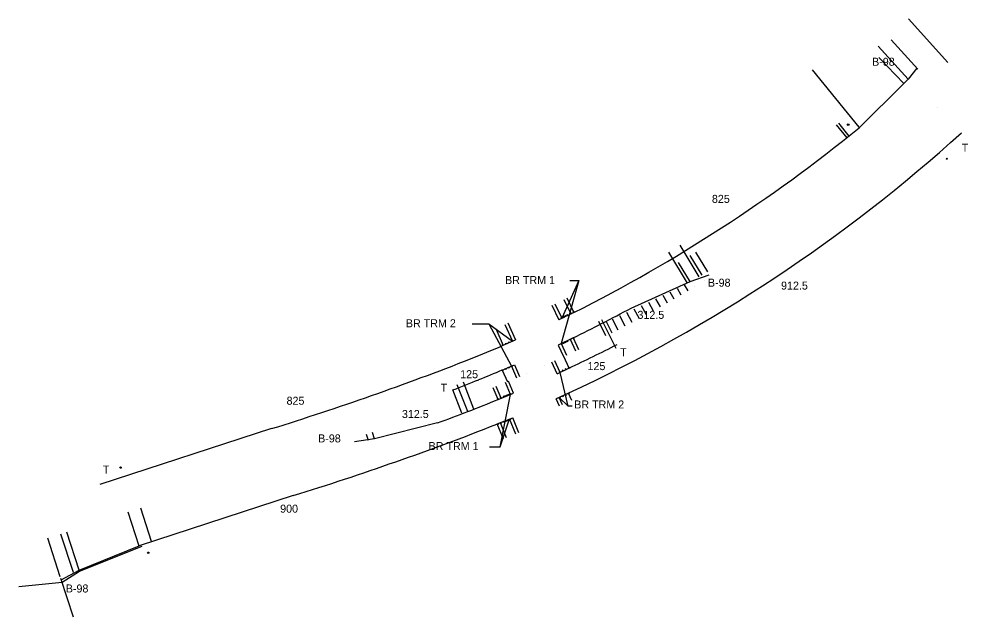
# Model space of a CAD drawing. Extents: x 1394788 to 1443949, y 571575 to 592763.
# Drawn here: x 1434855 to 1436634, y 586575 to 587696 of the extents above; entities that cross this region are included whole.
import ezdxf

# ---------------------------------------------------------------- set-up
doc = ezdxf.new("R2010")
doc.units = 0
doc.layers.add('Level 24', color=7, linetype='Continuous')
doc.layers.add('Level 62', color=7, linetype='Continuous')

msp = doc.modelspace()

# ---------------------------------------------------------------- linework, layer by layer
at = {"layer": 'Level 24'}
for p, q in [((1436538.8, 587603.5), (1436522.4, 587582.8)), ((1436522.4, 587582.8), (1436514.1, 587574.8)), ((1436514.1, 587574.8), (1436430.5, 587492.1)), ((1436113.3, 587203.9), (1436149.3, 587216.3)), ((1436002.7, 587153.9), (1436113.3, 587203.9)), ((1435895.8, 587145.8), (1435867.7, 587132.1)), ((1435763.1, 587084.4), (1435786, 587094.3)), ((1435894.2, 587098.3), (1435866, 587084.8)), ((1435761.4, 587038), (1435784.3, 587047.8)), ((1435886.8, 587041.7), (1435863.5, 587030.5)), ((1435717.5, 587019.9), (1435717.5, 587019.9)), ((1435753.7, 586982.8), (1435782.6, 586994.9)), ((1435885.3, 586994.4), (1435862.5, 586984.1)), ((1435752, 586936.8), (1435781, 586948.6)), ((1435328.7, 586928.1), (1435007.2, 586823.7)), ((1435639.8, 586938.7), (1435522, 586909.1)), ((1435751.2, 586936.4), (1435751.1, 586936.4)), ((1435522, 586909.1), (1435484.4, 586903.4)), ((1435369.5, 586802.5), (1435369.5, 586802.5)), ((1434968.3, 586662.6), (1435080.4, 586708.7)), ((1434934.6, 586644.8), (1434968.3, 586662.6))]:
    msp.add_line(p, q, dxfattribs=at)
for points in [[(1435872.6, 587134.5), (1435871.9, 587135.9), (1435873.4, 587136.6), (1435874.1, 587135.2)], [(1435875.4, 587135.9), (1435874.7, 587137.3), (1435876.2, 587138), (1435876.9, 587136.6)], [(1435878.2, 587137.2), (1435877.5, 587138.6), (1435879, 587139.4), (1435879.7, 587138)], [(1435881, 587138.6), (1435880.3, 587140), (1435881.8, 587140.7), (1435882.5, 587139.3)], [(1435883.8, 587140), (1435883.1, 587141.4), (1435884.6, 587142.1), (1435885.3, 587140.7)], [(1435889.4, 587142.7), (1435888.7, 587144.2), (1435890.2, 587144.9), (1435890.9, 587143.5)], [(1435895, 587145.5), (1435894.3, 587146.9), (1435895.8, 587147.7), (1435896.5, 587146.3)], [(1435762.3, 587084), (1435761.7, 587085.5), (1435763.2, 587086.1), (1435763.9, 587084.7)], [(1435768.1, 587086.5), (1435767.4, 587087.9), (1435769, 587088.6), (1435769.6, 587087.1)], [(1435773.8, 587089), (1435773.2, 587090.4), (1435774.7, 587091.1), (1435775.3, 587089.6)], [(1435779.5, 587091.4), (1435778.9, 587092.9), (1435780.5, 587093.5), (1435781.1, 587092.1)], [(1435871.6, 587085.7), (1435870.9, 587087.1), (1435872.4, 587087.9), (1435873.1, 587086.4)], [(1435874.4, 587087.1), (1435873.7, 587088.5), (1435875.3, 587089.2), (1435875.9, 587087.8)], [(1435877.2, 587088.4), (1435876.6, 587089.8), (1435878.1, 587090.6), (1435878.7, 587089.1)], [(1435880.1, 587089.8), (1435879.4, 587091.2), (1435880.9, 587091.9), (1435881.6, 587090.5)], [(1435882.9, 587091.1), (1435882.2, 587092.5), (1435883.7, 587093.3), (1435884.4, 587091.8)], [(1435888.5, 587093.8), (1435887.8, 587095.2), (1435889.3, 587096), (1435890, 587094.6)], [(1435894.1, 587096.6), (1435893.5, 587098), (1435895, 587098.7), (1435895.6, 587097.3)], [(1435761.2, 587036.3), (1435760.6, 587037.8), (1435762.1, 587038.4), (1435762.7, 587037)], [(1435766.9, 587038.7), (1435766.3, 587040.2), (1435767.9, 587040.8), (1435768.5, 587039.4)], [(1435772.7, 587041.2), (1435772.1, 587042.6), (1435773.6, 587043.3), (1435774.2, 587041.8)], [(1435778.4, 587043.6), (1435777.8, 587045), (1435779.4, 587045.7), (1435780, 587044.3)], [(1435869.1, 587033.3), (1435868.5, 587034.7), (1435870, 587035.4), (1435870.6, 587034)], [(1435874.8, 587035.9), (1435874.1, 587037.4), (1435875.6, 587038.1), (1435876.3, 587036.7)], [(1435880.4, 587038.6), (1435879.8, 587040), (1435881.3, 587040.8), (1435881.9, 587039.3)], [(1435886.1, 587041.3), (1435885.4, 587042.7), (1435886.9, 587043.4), (1435887.6, 587042)], [(1435885.1, 586992.8), (1435884.5, 586994.2), (1435886, 586994.9), (1435886.6, 586993.5)], [(1435752.8, 586982.5), (1435752.2, 586983.9), (1435753.7, 586984.6), (1435754.4, 586983.1)], [(1435758.6, 586984.9), (1435758, 586986.3), (1435759.5, 586987), (1435760.1, 586985.5)], [(1435764.4, 586987.2), (1435763.8, 586988.7), (1435765.3, 586989.3), (1435765.9, 586987.9)], [(1435767.3, 586988.4), (1435766.7, 586989.9), (1435768.2, 586990.5), (1435768.8, 586989.1)], [(1435770.1, 586989.6), (1435769.5, 586991.1), (1435771.1, 586991.7), (1435771.7, 586990.3)], [(1435773, 586990.8), (1435772.4, 586992.3), (1435774, 586992.9), (1435774.6, 586991.5)], [(1435775.9, 586992), (1435775.3, 586993.5), (1435776.9, 586994.1), (1435777.5, 586992.7)], [(1435868.1, 586984.9), (1435867.5, 586986.3), (1435869, 586987), (1435869.6, 586985.6)], [(1435873.8, 586987.5), (1435873.1, 586988.9), (1435874.7, 586989.6), (1435875.3, 586988.2)], [(1435879.5, 586990.1), (1435878.8, 586991.6), (1435880.3, 586992.3), (1435881, 586990.8)], [(1435763.4, 586939.8), (1435762.8, 586941.2), (1435764.4, 586941.9), (1435765, 586940.4)], [(1435766.3, 586940.9), (1435765.7, 586942.4), (1435767.3, 586943), (1435767.9, 586941.6)], [(1435769.2, 586942.1), (1435768.6, 586943.6), (1435770.2, 586944.2), (1435770.8, 586942.7)], [(1435772.1, 586943.3), (1435771.5, 586944.7), (1435773.1, 586945.4), (1435773.7, 586943.9)], [(1435775, 586944.5), (1435774.4, 586945.9), (1435776, 586946.5), (1435776.5, 586945.1)], [(1435751.8, 586935.1), (1435751.2, 586936.6), (1435752.8, 586937.2), (1435753.4, 586935.8)], [(1435757.6, 586937.4), (1435757, 586938.9), (1435758.6, 586939.5), (1435759.2, 586938.1)]]:
    msp.add_lwpolyline(points, close=True, dxfattribs=at)
msp.add_lwpolyline([(1435369.5, 586802.5), (1435080.4, 586708.7)], dxfattribs=at)
for centre, radius, start, end in [((1434643.7, 589670.2), 2949.6, 294.8914, 312.1307), ((1434568.8, 589780.8), 2950.3, 296.7297, 309.125), ((1434653.9, 589654.1), 2840.8, 295.8869, 298.3505), ((1433689.9, 591964.3), 5302.1, 292.2998, 293.0177), ((1434653.9, 589654.1), 2888.8, 295.2645, 297.2479), ((1433674.6, 592246.1), 5569.3, 287.278, 291.3457), ((1434653.9, 589654.1), 2840.8, 291.9864, 292.9439), ((1434580.9, 589836.4), 3037.2, 290.9855, 291.9756), ((1434653.9, 589654.1), 2888.8, 289.9535, 292.378), ((1433712.1, 592139.3), 5588.2, 287.2529, 291.4008), ((1434653.9, 589654.1), 2930.8, 291.9864, 292.0045)]:
    msp.add_arc(centre, radius, start, end, dxfattribs=at)
at = {"layer": 'Level 62'}
for p, q in [((1436522.6, 587695.9), (1436596.7, 587614.1)), ((1436490.4, 587656.9), (1436540.3, 587601.8)), ((1436466.2, 587644.9), (1436522.4, 587582.8)), ((1436467.1, 587623.6), (1436514.1, 587574.8)), ((1436342.4, 587600.4), (1436429.9, 587493)), ((1436576.7, 587530.4), (1436576.7, 587530.4)), ((1436387.6, 587497.8), (1436407.2, 587473.3)), ((1436391.5, 587500.9), (1436411.1, 587476.5)), ((1436094.2, 587271.8), (1436130.1, 587212.4)), ((1436072.8, 587258.9), (1436108, 587200.8)), ((1436112.8, 587252.6), (1436135.3, 587215.6)), ((1436123.5, 587259.1), (1436146, 587222.1)), ((1436091.4, 587239.6), (1436113.9, 587202.6)), ((1435905.1, 587205.8), (1435871.7, 587087.5)), ((1435905.1, 587205.8), (1435873.3, 587134.9)), ((1435887.8, 587205.8), (1435905.1, 587205.8)), ((1436089, 587191.2), (1436096.2, 587178.8)), ((1436102.4, 587197.8), (1436109.2, 587186.4)), ((1436122.1, 587194), (1436122.1, 587194)), ((1436141.3, 587205.7), (1436141.3, 587205.7)), ((1435882.7, 587173), (1435895.8, 587145.8)), ((1436062.2, 587178), (1436070.2, 587163.8)), ((1436075.6, 587184.5), (1436083.2, 587171.3)), ((1436096.2, 587178.8), (1436096.2, 587178.8)), ((1436109.2, 587186.4), (1436109.2, 587186.4)), ((1435854.5, 587159.3), (1435867.7, 587132.1)), ((1435860.2, 587162.1), (1435873.3, 587134.9)), ((1435877, 587170.2), (1435890.2, 587143)), ((1436021.7, 587158.8), (1436030.9, 587141.9)), ((1436035.2, 587165.1), (1436044.1, 587149.1)), ((1436048.7, 587171.5), (1436057.2, 587156.5)), ((1436057.2, 587156.5), (1436057.2, 587156.5)), ((1436070.2, 587163.8), (1436070.2, 587163.8)), ((1436083.2, 587171.3), (1436083.2, 587171.3)), ((1435980.9, 587140.2), (1435991.3, 587120.6)), ((1435994.5, 587146.3), (1436004.5, 587127.6)), ((1436008.1, 587152.5), (1436017.7, 587134.7)), ((1436030.9, 587141.9), (1436030.9, 587141.9)), ((1436044.1, 587149.1), (1436044.1, 587149.1)), ((1435704.8, 587124.6), (1435736, 587124.6)), ((1435736, 587124.6), (1435780.3, 587091.8)), ((1435736, 587124.6), (1435778.6, 587045.4)), ((1435766.3, 587123.6), (1435780.3, 587091.8)), ((1435772.1, 587126.1), (1435786, 587094.3)), ((1435955.8, 587102.2), (1435942.1, 587128.8)), ((1435975.2, 587078.4), (1435947.8, 587131.8)), ((1435956, 587129), (1435966.9, 587107.9)), ((1435967.3, 587134.2), (1435978, 587113.6)), ((1435991.3, 587120.6), (1435991.3, 587120.6)), ((1436004.5, 587127.6), (1436004.5, 587127.6)), ((1436017.7, 587134.7), (1436017.7, 587134.7)), ((1435749.2, 587116), (1435763.1, 587084.2)), ((1435966.9, 587107.9), (1435966.9, 587107.9)), ((1435978, 587113.6), (1435978, 587113.6)), ((1435866, 587084.8), (1435876.3, 587063.1)), ((1435871.7, 587087.5), (1435882, 587065.8)), ((1435888.6, 587095.5), (1435898.9, 587073.9)), ((1435894.2, 587098.3), (1435904.5, 587076.5)), ((1435882, 587065.8), (1435882, 587065.8)), ((1435902.1, 587075.5), (1435902.1, 587075.5)), ((1435784.3, 587047.8), (1435793.8, 587025.8)), ((1435864.2, 587031), (1435854.1, 587052.8)), ((1435859.8, 587055.4), (1435859.8, 587055.4)), ((1435869.9, 587033.6), (1435859.8, 587055.4)), ((1435886.9, 587041.5), (1435876.8, 587063.3)), ((1435761.4, 587038), (1435770.9, 587015.9)), ((1435778.6, 587045.4), (1435788.1, 587023.3)), ((1435806.8, 587031.5), (1435806.8, 587031.5)), ((1435840.9, 587046.7), (1435840.9, 587046.7)), ((1435885.1, 586970.1), (1435869.9, 587033.6)), ((1435708.3, 586964.5), (1435688.7, 587014.9)), ((1435767.5, 587014.5), (1435767.5, 587014.5)), ((1435776.8, 586992.4), (1435767.5, 587014.5)), ((1435782.6, 586994.9), (1435773.2, 587017)), ((1435788.1, 587023.3), (1435788.1, 587023.3)), ((1435685.6, 586956.9), (1435668.6, 587000.7)), ((1435696.6, 586960), (1435677.1, 587010.3)), ((1435753.8, 586982.7), (1435744.5, 587004.8)), ((1435749.9, 587007.2), (1435749.9, 587007.2)), ((1435759.5, 586985.1), (1435750.2, 587007.3)), ((1435891.5, 586980.7), (1435885.3, 586994.4)), ((1435757.7, 586893.9), (1435776.8, 586992.4)), ((1435868.8, 586970.4), (1435862.5, 586984.1)), ((1435874.5, 586973), (1435868.2, 586986.7)), ((1435885.1, 586970.1), (1435868.2, 586986.7)), ((1435892.4, 586970.1), (1435885.1, 586970.1)), ((1435757.7, 586893.9), (1435775.2, 586946.2)), ((1435786.9, 586918), (1435775.2, 586946.2)), ((1435792.6, 586920.4), (1435781, 586948.6)), ((1435763.8, 586908.5), (1435752, 586936.8)), ((1435769.5, 586910.8), (1435757.9, 586939.1)), ((1435507.1, 586917.3), (1435507.1, 586917.3)), ((1435510.9, 586905.9), (1435507.1, 586917.3)), ((1435522, 586909.1), (1435518, 586921)), ((1435737.3, 586893.9), (1435757.7, 586893.9)), ((1435080.6, 586707.9), (1435060, 586771.4)), ((1435104.1, 586716.4), (1435083.8, 586779.2)), ((1434957.6, 586658.3), (1434934.1, 586730.6)), ((1434968.3, 586662.6), (1434945, 586734.1)), ((1434932.9, 586650.3), (1434909.4, 586722.6)), ((1434969, 586660.7), (1435086.3, 586707.6)), ((1434936.2, 586640.1), (1434969, 586660.7)), ((1434855.4, 586632.5), (1434936.2, 586640.1)), ((1434957.3, 586575), (1434933.8, 586647.3))]:
    msp.add_line(p, q, dxfattribs=at)
for centre, radius in [((1436409.9, 587497.8), 1.5), ((1436594.6, 587433.9), 1), ((1435045.9, 586855.2), 1.25), ((1435097.8, 586695.4), 1.25)]:
    msp.add_circle(centre, radius, dxfattribs=at)

# ---------------------------------------------------------------- texts
for s, p in [('B-98', (1436454.6, 587608.2)), ('T', (1436622.7, 587447.2)), ('825', (1436154.4, 587351.2)), ('BR TRM 1', (1435766.6, 587199.1)), ('B-98', (1436146.9, 587194.2)), ('912.5', (1436284, 587188.7)), ('312.5', (1436014.8, 587133.9)), ('BR TRM 2', (1435580.7, 587118.1)), ('T', (1435982.4, 587063.8)), ('125', (1435921.2, 587037.8)), ('125', (1435682.5, 587022.6)), ('T', (1435646, 586997.3)), ('825', (1435357, 586972.9)), ('BR TRM 2', (1435896.3, 586965.9)), ('312.5', (1435573.3, 586948)), ('B-98', (1435416.2, 586902.3)), ('BR TRM 1', (1435623.3, 586887.9)), ('T', (1435012.5, 586843.9)), ('900', (1435345, 586770.6)), ('B-98', (1434943.1, 586621))]:
    msp.add_text(s, height=15, dxfattribs=at).set_placement(p)

doc.saveas('drawing.dxf')
